// Mitsubishi GX Works2 project: 电机正反转例程   PLC: FX1S

PROGRAM MAIN
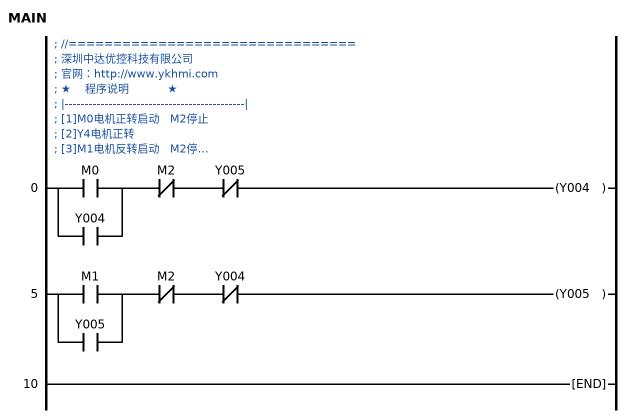
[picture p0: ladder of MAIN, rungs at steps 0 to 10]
; //================================
; 深圳中达优控科技有限公司
; 官网：http://www.ykhmi.com
; ★    程序说明           ★
; |---------------------------------------------|
; [1]M0电机正转启动   M2停止
; [2]Y4电机正转
; [3]M1电机反转启动   M2停止
; [4]Y5电机反转
; 
0     LD      M0
      OR      Y004
      ANI     M2
      ANI     Y005
      OUT     Y004
5     LD      M1
      OR      Y005
      ANI     M2
      ANI     Y004
      OUT     Y005
10    END
END_PROGRAM
